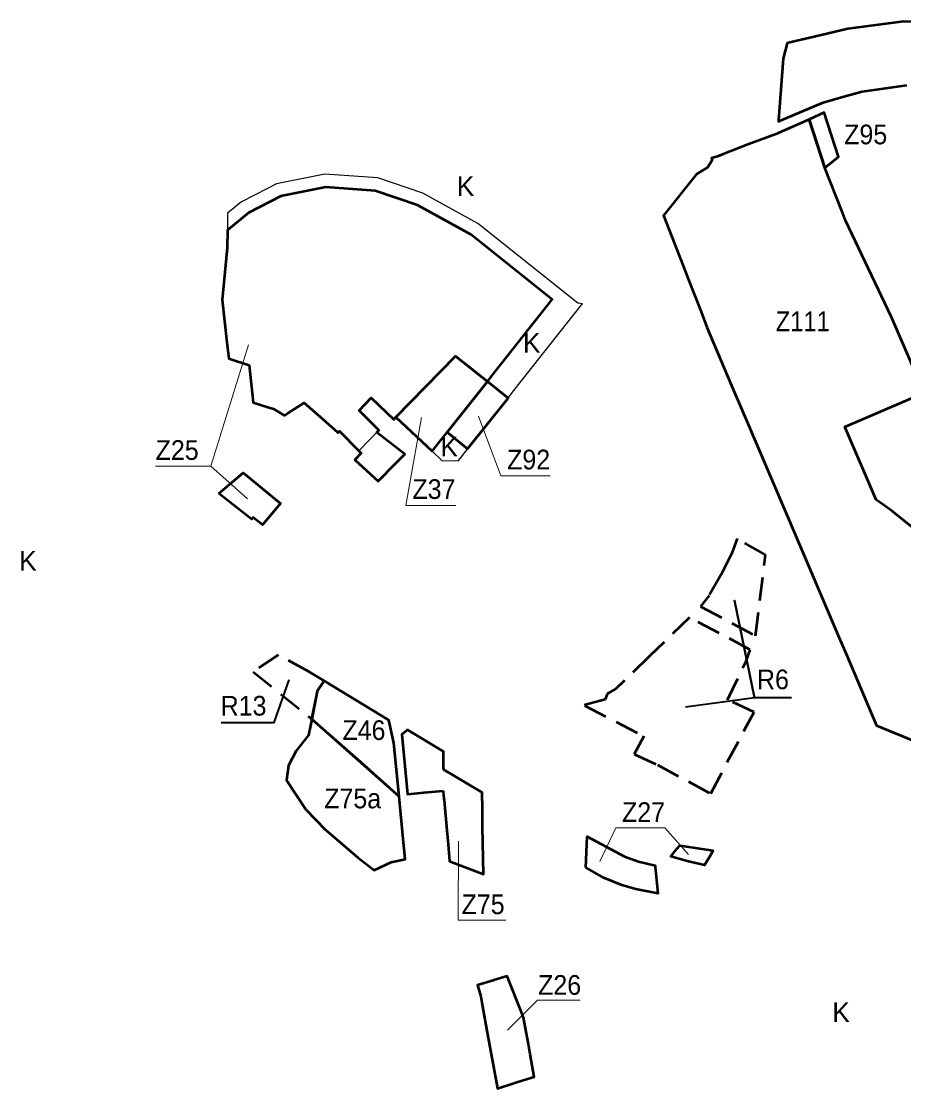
# Model space of a CAD drawing. Extents: x -650246 to -642674, y -1074280 to -1066767.
# Drawn here: x -650246 to -649169, y -1070473 to -1069171 of the extents above; entities that cross this region are included whole.
import ezdxf

# ---------------------------------------------------------------- set-up
doc = ezdxf.new("R2010")
doc.units = 0
doc.header["$LTSCALE"] = 9.6
doc.linetypes.add('MEDIUM_DASHED', pattern=[4.5, 3, -1.5])
for name, color, linetype, lineweight in [('42', 7, 'Continuous', 25), ('44', 7, 'Continuous', 53), ('45', 7, 'Continuous', 53), ('46', 7, 'Continuous', 13), ('48', 7, 'Continuous', 13), ('61', 7, 'MEDIUM_DASHED', 53), ('62', 7, 'Continuous', 35)]:
    doc.layers.add(name, color=color, linetype=linetype, lineweight=lineweight)

msp = doc.modelspace()

# ---------------------------------------------------------------- linework, layer by layer
at = {"layer": '42'}
msp.add_lwpolyline([(-649641.978, -1069618.226), (-649572.972, -1069530.758), (-649561.91, -1069516.78), (-649561.17, -1069515.83), (-649566.951, -1069515.099), (-649688.625, -1069418.156), (-649755.971, -1069381.179), (-649810.846, -1069362.154), (-649875.434, -1069357.751), (-649934.363, -1069369.537), (-649945.397, -1069375.277), (-649977.239, -1069391.714), (-649994.329, -1069405.451), (-649994.293, -1069425.949), (-649994.53, -1069447.61), (-650000.59, -1069511.15), (-649992.59, -1069582.88), (-649967.81, -1069590.74), (-649962.71, -1069636.46), (-649960.314, -1069637.218), (-649944.963, -1069642.085), (-649938.2, -1069644.23), (-649924.8, -1069652.19), (-649920.45, -1069649.53), (-649900.64, -1069636.78), (-649877.82, -1069656.83), (-649859.96, -1069672.53), (-649859.17, -1069673.22), (-649857.49, -1069671.46), (-649833.94, -1069695.24), (-649833.94, -1069695.24), (-649819.98, -1069680.92), (-649809.47, -1069670.13), (-649833.38, -1069646.08), (-649818.71, -1069630.64), (-649791.3, -1069657.21), (-649788.91, -1069654.4), (-649744.517, -1069695.746), (-649744.517, -1069695.746), (-649732.52, -1069706.92), (-649712.64, -1069707.43), (-649708.322, -1069702.293), (-649701.211, -1069692.826), (-649651.773, -1069630.879), (-649651.846, -1069630.821), (-649651.846, -1069630.82)], close=True, dxfattribs=at)
at = {"layer": '44'}
msp.add_lwpolyline([(-649076.02, -1069172.683), (-649169.781, -1069171.432), (-649237.512, -1069180.731), (-649277.021, -1069189.913), (-649306.455, -1069196.754), (-649311.633, -1069197.958), (-649316.47, -1069216.91), (-649321.32, -1069281.47), (-649322.09, -1069291.73), (-649322.22, -1069293.54), (-649319.72, -1069292.47), (-649267.5, -1069270.41), (-649242.5, -1069263.3), (-649220.18, -1069257.03), (-649202.63, -1069254.4), (-649165.62, -1069249.43)], dxfattribs=at)
msp.add_lwpolyline([(-649701.211, -1069692.826), (-649651.773, -1069630.879), (-649677.124, -1069610.681), (-649726.033, -1069672.415)], close=True, dxfattribs=at)
at = {"layer": '44', "lineweight": 13}
msp.add_lwpolyline([(-649600.782, -1069725.864), (-649660.57, -1069725.864), (-649688.04, -1069653.176)], dxfattribs=at)
at = {"layer": '45'}
for points in [[(-649144.57, -1069624.6), (-649184.1, -1069532.2), (-649240.202, -1069414.528), (-649244.08, -1069404.753), (-649265.774, -1069350.068), (-649284.695, -1069291.033), (-649321.69, -1069307.61), (-649324.3, -1069308.59), (-649359.48, -1069321.82), (-649389.4, -1069333.35), (-649396.52, -1069336.09), (-649403.92, -1069338.26), (-649403.03, -1069340.66), (-649408.81, -1069349.89), (-649422.19, -1069357.99), (-649462.25, -1069408.32), (-649435.578, -1069476.772), (-649435.578, -1069476.772), (-649431.761, -1069486.57), (-649416.52, -1069525.68), (-649409.355, -1069544.517), (-649388.438, -1069594.296), (-649379.32, -1069615.71), (-649364.44, -1069650.55), (-649312.03, -1069773.33), (-649246.81, -1069926.27), (-649246.81, -1069926.27), (-649239.635, -1069943.094), (-649202.375, -1070030.469), (-649202.375, -1070030.469), (-649085.737, -1070078.201)], [(-649154.76, -1069792.11), (-649184.05, -1069768.45), (-649200.64, -1069756.53), (-649202.99, -1069754.99), (-649241.11, -1069665.9), (-649155.082, -1069629.097)], [(-649730.837, -1070084.028), (-649730.6, -1070061.98), (-649774.73, -1070035.58), (-649781.53, -1070041.2), (-649774.45, -1070113.92), (-649754.82, -1070111.89), (-649731.12, -1070109.96)], [(-649730.837, -1070084.028), (-649730.6, -1070061.98), (-649774.73, -1070035.58), (-649781.53, -1070041.2), (-649774.45, -1070113.92), (-649754.82, -1070111.89), (-649731.12, -1070109.96)], [(-649731.12, -1070109.96), (-649730.57, -1070115.76), (-649730, -1070122.01), (-649726.22, -1070162.75), (-649725.49, -1070170.64), (-649723.17, -1070195.81), (-649682.04, -1070211.58), (-649683.12, -1070154.14), (-649682.98, -1070132.1), (-649683.57, -1070112.05), (-649717.72, -1070091.61), (-649730.837, -1070084.028)], [(-649731.12, -1070109.96), (-649730.57, -1070115.76), (-649730, -1070122.01), (-649726.22, -1070162.75), (-649725.49, -1070170.64), (-649723.17, -1070195.81), (-649682.04, -1070211.58), (-649683.12, -1070154.14), (-649682.98, -1070132.1), (-649683.57, -1070112.05), (-649717.72, -1070091.61), (-649730.837, -1070084.028)]]:
    msp.add_lwpolyline(points, dxfattribs=at)
for points in [[(-649265.774, -1069350.068), (-649249.069, -1069336.66), (-649266.331, -1069282.804), (-649284.695, -1069291.033)], [(-649994.293, -1069425.949), (-649994.293, -1069425.949), (-649994.53, -1069447.61), (-650000.59, -1069511.15), (-649994.794, -1069563.119), (-649992.59, -1069582.88), (-649967.81, -1069590.74), (-649962.71, -1069636.46), (-649944.963, -1069642.085), (-649938.2, -1069644.23), (-649924.8, -1069652.19), (-649920.45, -1069649.53), (-649900.64, -1069636.78), (-649900.64, -1069636.78), (-649877.82, -1069656.83), (-649859.96, -1069672.53), (-649859.17, -1069673.22), (-649857.49, -1069671.46), (-649833.94, -1069695.24), (-649831.087, -1069698.045), (-649838.99, -1069706.15), (-649819.9, -1069723.61), (-649810.41, -1069732.28), (-649807.66, -1069729.46), (-649792.13, -1069713.65), (-649777.94, -1069699.2), (-649812.153, -1069672.884), (-649809.47, -1069670.13), (-649833.38, -1069646.08), (-649818.71, -1069630.64), (-649791.3, -1069657.21), (-649788.91, -1069654.4), (-649715.908, -1069579.804), (-649677.124, -1069610.681), (-649667.188, -1069598.14), (-649598.004, -1069510.814), (-649697.525, -1069431.522), (-649762.488, -1069395.854), (-649814.067, -1069377.972), (-649874.391, -1069373.859), (-649929.015, -1069384.784), (-649968.465, -1069405.189), (-649994.293, -1069425.949), (-649994.293, -1069425.949)], [(-649788.91, -1069654.4), (-649744.517, -1069695.746), (-649677.124, -1069610.681), (-649715.908, -1069579.804)], [(-649788.91, -1069654.4), (-649744.517, -1069695.746), (-649677.124, -1069610.681), (-649715.908, -1069579.804)], [(-650004.59, -1069747.27), (-649974.86, -1069721.96), (-649966.52, -1069728.87), (-649929.38, -1069759.65), (-649951.56, -1069785.42), (-649963, -1069776.7), (-649965, -1069778.7)], [(-650004.59, -1069747.27), (-649974.86, -1069721.96), (-649966.52, -1069728.87), (-649929.38, -1069759.65), (-649951.56, -1069785.42), (-649963, -1069776.7), (-649965, -1069778.7)], [(-649891.21, -1070022.68), (-649832.007, -1070074.751), (-649784.87, -1070116.76), (-649791.31, -1070051.51), (-649797.45, -1070023.77), (-649876.31, -1069975.93), (-649884.59, -1069988.57)], [(-649891.21, -1070022.68), (-649832.007, -1070074.751), (-649784.87, -1070116.76), (-649791.31, -1070051.51), (-649797.45, -1070023.77), (-649876.31, -1069975.93), (-649884.59, -1069988.57)], [(-649891.21, -1070022.68), (-649895.45, -1070042.15), (-649910.34, -1070061.29), (-649919.55, -1070079.01), (-649922.3, -1070096.9), (-649898.55, -1070132.9), (-649874.94, -1070157.19), (-649835.28, -1070191.27), (-649815.33, -1070206.63), (-649794.37, -1070197.2), (-649777.29, -1070193.57), (-649779.75, -1070168.69), (-649784.87, -1070116.76)], [(-649557.21, -1070203.53), (-649555.44, -1070165.91), (-649532.57, -1070178.08), (-649509.72, -1070190.24), (-649492.67, -1070196.34), (-649472.6, -1070201.15), (-649472.43, -1070202.9), (-649469.176, -1070235.365), (-649496, -1070230), (-649513, -1070225), (-649535, -1070216)], [(-649557.21, -1070203.53), (-649555.44, -1070165.91), (-649532.57, -1070178.08), (-649509.72, -1070190.24), (-649492.67, -1070196.34), (-649472.6, -1070201.15), (-649472.43, -1070202.9), (-649469.176, -1070235.365), (-649496, -1070230), (-649513, -1070225), (-649535, -1070216)], [(-649442.63, -1070176.69), (-649402.29, -1070182.92), (-649404.2, -1070187.43), (-649412.2, -1070200.71), (-649433.3, -1070195.89), (-649453.27, -1070190.02), (-649446.19, -1070180.76)], [(-649442.63, -1070176.69), (-649402.29, -1070182.92), (-649404.2, -1070187.43), (-649412.2, -1070200.71), (-649433.3, -1070195.89), (-649453.27, -1070190.02), (-649446.19, -1070180.76)], [(-649678.92, -1070395.81), (-649672.83, -1070429.29), (-649672.49, -1070431.16), (-649664.82, -1070473.32), (-649644.74, -1070466.68), (-649640.18, -1070465.2), (-649624.33, -1070460.03), (-649620.17, -1070459.09), (-649624.97, -1070431.24), (-649627.13, -1070419.17), (-649633, -1070386.46), (-649635.52, -1070380.14), (-649653.03, -1070336.2), (-649669.24, -1070341.04), (-649670.28, -1070341.35), (-649689.02, -1070346.94), (-649685.31, -1070360.88), (-649683.08, -1070373.11)], [(-649678.92, -1070395.81), (-649672.83, -1070429.29), (-649672.49, -1070431.16), (-649664.82, -1070473.32), (-649644.74, -1070466.68), (-649640.18, -1070465.2), (-649624.33, -1070460.03), (-649620.17, -1070459.09), (-649624.97, -1070431.24), (-649627.13, -1070419.17), (-649633, -1070386.46), (-649635.52, -1070380.14), (-649653.03, -1070336.2), (-649669.24, -1070341.04), (-649670.28, -1070341.35), (-649689.02, -1070346.94), (-649685.31, -1070360.88), (-649683.08, -1070373.11)]]:
    msp.add_lwpolyline(points, close=True, dxfattribs=at)
at = {"layer": '46'}
for points in [[(-650082.06, -1069714.05), (-650014.296, -1069714.05), (-649968.712, -1069565.984), (-650014.296, -1069714.05), (-649969.577, -1069753.88)], [(-650082.06, -1069714.05), (-650014.296, -1069714.05), (-649968.712, -1069565.984), (-650014.296, -1069714.05), (-649969.577, -1069753.88)], [(-649715.535, -1069761.925), (-649776.818, -1069761.925), (-649757.387, -1069654.603)], [(-649715.535, -1069761.925), (-649776.818, -1069761.925), (-649757.387, -1069654.603)], [(-649431.69, -1070187.9), (-649460.604, -1070155.007), (-649520.489, -1070155.007), (-649540.207, -1070196.319)], [(-649654.738, -1070267.746), (-649712.819, -1070267.746), (-649712.819, -1070267.746), (-649712.586, -1070171.248)], [(-649563.99, -1070365.19), (-649615.905, -1070365.19), (-649652.601, -1070401.913)], [(-649563.99, -1070365.19), (-649615.905, -1070365.19), (-649652.601, -1070401.913)]]:
    msp.add_lwpolyline(points, dxfattribs=at)
at = {"layer": '61'}
for points in [[(-649372.56, -1069802.33), (-649379.19, -1069820.24), (-649391.86, -1069846.18), (-649406.53, -1069871.59), (-649417.234, -1069885.193), (-649350.222, -1069920.873), (-649338, -1069822)], [(-649430.515, -1069898.514), (-649479.08, -1069945.53), (-649520.6, -1069985.72), (-649530.31, -1069991.5), (-649530.99, -1069991.9), (-649533.61, -1069998.6), (-649557.92, -1070005.19), (-649558.56, -1070006.13), (-649486.5, -1070043.26), (-649497.95, -1070065.49), (-649469.85, -1070078.3), (-649404.76, -1070113.41), (-649360.74, -1070030.35), (-649351.66, -1070014.26), (-649384.249, -1069998.959), (-649361.46, -1069951.93), (-649356.458, -1069937.945)], [(-649931.76, -1069944.31), (-649962.859, -1069964.896), (-649891.21, -1070022.68), (-649884.59, -1069988.57), (-649876.31, -1069975.93), (-649894.68, -1069964.78)]]:
    msp.add_lwpolyline(points, close=True, dxfattribs=at)
at = {"layer": '62'}
for points in [[(-649306.343, -1069996.537), (-649351.328, -1069996.537), (-649375.864, -1069878.046), (-649351.328, -1069996.537), (-649435.663, -1070007.798)], [(-650001.823, -1070026.616), (-649937.373, -1070026.616), (-649918.861, -1069974.471)]]:
    msp.add_lwpolyline(points, dxfattribs=at)
at = {"layer": '62', "lineweight": 13}
msp.add_lwpolyline([(-650001.823, -1070026.616), (-649937.373, -1070026.616), (-649918.861, -1069974.471)], dxfattribs=at)

# ---------------------------------------------------------------- texts
at = {"layer": '44', "width": 0.95}
for s, p in [('Z95', (-649242.024, -1069321.399)), ('Z92', (-649653.123, -1069717.932))]:
    msp.add_text(s, height=24, dxfattribs=at).set_placement(p)
at = {"layer": '46'}
for s, width, p in [('Z111', 0.9, (-649325.444, -1069549.35)), ('Z111', 0.9, (-649325.444, -1069549.35)), ('Z25', 0.95, (-650081.8, -1069706.363)), ('Z25', 0.95, (-650081.8, -1069706.363)), ('Z37', 0.95, (-649768.624, -1069753.993)), ('Z37', 0.95, (-649768.624, -1069753.993)), ('Z46', 0.95, (-649853.994, -1070048.002)), ('Z46', 0.95, (-649853.994, -1070048.002)), ('Z75a', 0.95, (-649876.242, -1070131.383)), ('Z27', 0.95, (-649512.965, -1070148.029)), ('Z75', 0.95, (-649708.673, -1070260.465)), ('Z26', 0.95, (-649615.355, -1070358.803)), ('Z26', 0.95, (-649615.355, -1070358.803))]:
    msp.add_text(s, height=24, dxfattribs=dict(at, width=width)).set_placement(p)
at = {"layer": '48'}
for p in [(-649714.485, -1069384.456), (-649714.485, -1069384.456), (-649633.851, -1069575.59), (-649734.395, -1069702.217), (-650248.205, -1069841.413), (-650248.205, -1069841.413), (-649256.486, -1070392.051)]:
    msp.add_text('K', height=24, dxfattribs=at).set_placement(p)
at = {"layer": '62', "width": 0.95}
for s, p in [('R6', (-649348.349, -1069986.108)), ('R13', (-650002.521, -1070018.261)), ('R13', (-650002.521, -1070018.261))]:
    msp.add_text(s, height=24, dxfattribs=at).set_placement(p)

doc.saveas('drawing.dxf')
